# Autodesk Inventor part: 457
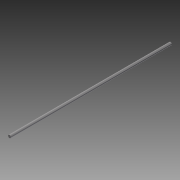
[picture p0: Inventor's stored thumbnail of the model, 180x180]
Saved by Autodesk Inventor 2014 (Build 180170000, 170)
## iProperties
Created: 2013-12
Part Number: 457
Material: Stainless Steel
Document SubType Name: Modeling
Designer: Bram
Density: 8.08 g/cm^3
Appearance: Semi-Polished
Author: Bram
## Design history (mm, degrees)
sketch "Sketch1"
  geometry: C1 r 4 at (0, 0); 1 further point
  constraints: 1 centre point, 1 coincident
  dimensions: "d0" = 8 diameter of C1
extrude "Extrusion1" new body sketch "Sketch1" distance "d1" = 457; taper "d2" = 0 deg
body "Solid1"
